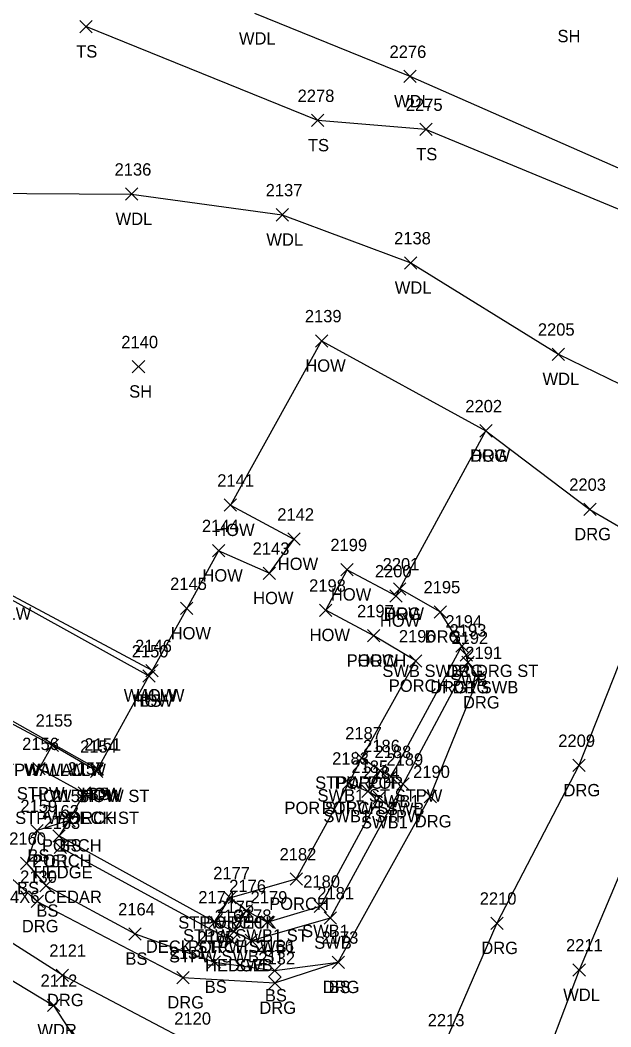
# Model space of a CAD drawing. Extents: x 1885914 to 1887218, y 756253 to 760620.
# Drawn here: x 1886470.3 to 1886566, y 760195 to 760358 of the extents above; entities that cross this region are included whole.
import ezdxf

# ---------------------------------------------------------------- set-up
doc = ezdxf.new("R2010")
doc.units = 0
for name, color, linetype in [('L_A', 7, 'Continuous'), ('L_C', 7, 'Continuous'), ('L_I', 7, 'Continuous'), ('L_TIC', 7, 'Continuous'), ('LAHR', 7, 'Continuous'), ('LAWA', 7, 'Continuous'), ('LBC', 7, 'Continuous'), ('LBF', 7, 'Continuous'), ('LELB', 7, 'Continuous'), ('LW', 7, 'Continuous'), ('R_A', 7, 'Continuous'), ('R_I', 7, 'Continuous'), ('R_TIC', 7, 'Continuous'), ('RDG', 7, 'Continuous'), ('RSW', 7, 'Continuous')]:
    doc.layers.add(name, color=color, linetype=linetype)

msp = doc.modelspace()

# ---------------------------------------------------------------- linework, layer by layer
at = {"layer": 'L_TIC'}
for points in [[(1886480, 760355.9), (1886482, 760357.9)], [(1886482, 760355.9), (1886480, 760357.9)], [(1886532.46, 760347.84), (1886534.46, 760349.84)], [(1886534.46, 760347.84), (1886532.46, 760349.84)], [(1886517.52, 760340.71), (1886519.52, 760342.71)], [(1886519.52, 760340.71), (1886517.52, 760342.71)], [(1886535.04, 760339.26), (1886537.04, 760341.26)], [(1886537.04, 760339.26), (1886535.04, 760341.26)], [(1886487.37, 760328.78), (1886489.37, 760330.78)], [(1886489.37, 760328.78), (1886487.37, 760330.78)], [(1886511.78, 760325.43), (1886513.78, 760327.43)], [(1886513.78, 760325.43), (1886511.78, 760327.43)], [(1886532.57, 760317.65), (1886534.57, 760319.65)], [(1886534.57, 760317.65), (1886532.57, 760319.65)], [(1886518.13, 760305.03), (1886520.13, 760307.03)], [(1886520.13, 760305.03), (1886518.13, 760307.03)], [(1886518.13, 760305.03), (1886520.13, 760307.03)], [(1886520.13, 760305.03), (1886518.13, 760307.03)], [(1886556.49, 760302.87), (1886558.49, 760304.87)], [(1886558.49, 760302.87), (1886556.49, 760304.87)], [(1886556.49, 760302.87), (1886558.49, 760304.87)], [(1886558.49, 760302.87), (1886556.49, 760304.87)], [(1886488.5, 760300.84), (1886490.5, 760302.84)], [(1886490.5, 760300.84), (1886488.5, 760302.84)], [(1886544.75, 760290.46), (1886546.75, 760292.46)], [(1886546.75, 760290.46), (1886544.75, 760292.46)], [(1886544.75, 760290.46), (1886546.75, 760292.46)], [(1886546.75, 760290.46), (1886544.75, 760292.46)], [(1886503.38, 760278.43), (1886505.38, 760280.43)], [(1886505.38, 760278.43), (1886503.38, 760280.43)], [(1886513.67, 760272.93), (1886515.67, 760274.93)], [(1886515.67, 760272.93), (1886513.67, 760274.93)], [(1886501.46, 760271.06), (1886503.46, 760273.06)], [(1886503.46, 760271.06), (1886501.46, 760273.06)], [(1886522.26, 760267.98), (1886524.26, 760269.98)], [(1886524.26, 760267.98), (1886522.26, 760269.98)], [(1886509.68, 760267.4), (1886511.68, 760269.4)], [(1886511.68, 760267.4), (1886509.68, 760269.4)], [(1886530.8, 760264.86), (1886532.8, 760266.86)], [(1886532.8, 760264.86), (1886530.8, 760266.86)], [(1886530.19, 760263.74), (1886532.19, 760265.74)], [(1886532.19, 760263.74), (1886530.19, 760265.74)], [(1886496.31, 760261.7), (1886498.31, 760263.7)], [(1886498.31, 760261.7), (1886496.31, 760263.7)], [(1886518.82, 760261.42), (1886520.82, 760263.42)], [(1886520.82, 760261.42), (1886518.82, 760263.42)], [(1886526.58, 760257.28), (1886528.58, 760259.28)], [(1886528.58, 760257.28), (1886526.58, 760259.28)], [(1886526.58, 760257.28), (1886528.58, 760259.28)], [(1886528.58, 760257.28), (1886526.58, 760259.28)], [(1886490.7, 760251.64), (1886492.7, 760253.64)], [(1886492.7, 760251.64), (1886490.7, 760253.64)], [(1886490.7, 760251.64), (1886492.7, 760253.64)], [(1886492.7, 760251.64), (1886490.7, 760253.64)], [(1886533.39, 760253.21), (1886535.39, 760255.21)], [(1886535.39, 760253.21), (1886533.39, 760255.21)], [(1886490.19, 760250.78), (1886492.19, 760252.78)], [(1886492.19, 760250.78), (1886490.19, 760252.78)], [(1886490.19, 760250.78), (1886492.19, 760252.78)], [(1886492.19, 760250.78), (1886490.19, 760252.78)], [(1886474.54, 760239.57), (1886476.54, 760241.57)], [(1886476.54, 760239.57), (1886474.54, 760241.57)], [(1886474.54, 760239.57), (1886476.54, 760241.57)], [(1886476.54, 760239.57), (1886474.54, 760241.57)], [(1886524.65, 760237.51), (1886526.65, 760239.51)], [(1886526.65, 760237.51), (1886524.65, 760239.51)], [(1886524.65, 760237.51), (1886526.65, 760239.51)], [(1886526.65, 760237.51), (1886524.65, 760239.51)], [(1886472.41, 760235.78), (1886474.41, 760237.78)], [(1886474.41, 760235.78), (1886472.41, 760237.78)], [(1886481.74, 760235.36), (1886483.74, 760237.36)], [(1886483.74, 760235.36), (1886481.74, 760237.36)], [(1886481.74, 760235.36), (1886483.74, 760237.36)], [(1886483.74, 760235.36), (1886481.74, 760237.36)], [(1886481.86, 760235.69), (1886483.86, 760237.69)], [(1886483.86, 760235.69), (1886481.86, 760237.69)], [(1886481.86, 760235.69), (1886483.86, 760237.69)], [(1886483.86, 760235.69), (1886481.86, 760237.69)], [(1886527.61, 760235.44), (1886529.61, 760237.44)], [(1886529.61, 760235.44), (1886527.61, 760237.44)], [(1886522.55, 760233.42), (1886524.55, 760235.42)], [(1886524.55, 760233.42), (1886522.55, 760235.42)], [(1886522.55, 760233.42), (1886524.55, 760235.42)], [(1886524.55, 760233.42), (1886522.55, 760235.42)], [(1886525.66, 760232.09), (1886527.66, 760234.09)], [(1886527.66, 760232.09), (1886525.66, 760234.09)], [(1886479.72, 760231.81), (1886481.72, 760233.81)], [(1886481.72, 760231.81), (1886479.72, 760233.81)], [(1886479.72, 760231.81), (1886481.72, 760233.81)], [(1886481.72, 760231.81), (1886479.72, 760233.81)], [(1886477.24, 760227.35), (1886479.24, 760229.35)], [(1886479.24, 760227.35), (1886477.24, 760229.35)], [(1886477.24, 760227.35), (1886479.24, 760229.35)], [(1886479.24, 760227.35), (1886477.24, 760229.35)], [(1886472.08, 760225.73), (1886474.08, 760227.73)], [(1886474.08, 760225.73), (1886472.08, 760227.73)], [(1886475.64, 760224.88), (1886477.64, 760226.88)], [(1886477.64, 760224.88), (1886475.64, 760226.88)], [(1886475.85, 760223.01), (1886477.85, 760225.01)], [(1886477.85, 760223.01), (1886475.85, 760225.01)], [(1886470.4, 760220.44), (1886472.4, 760222.44)], [(1886472.4, 760220.44), (1886470.4, 760222.44)], [(1886514.03, 760217.91), (1886516.03, 760219.91)], [(1886516.03, 760217.91), (1886514.03, 760219.91)], [(1886514.03, 760217.91), (1886516.03, 760219.91)], [(1886516.03, 760217.91), (1886514.03, 760219.91)], [(1886473.53, 760216.8), (1886475.53, 760218.8)], [(1886475.53, 760216.8), (1886473.53, 760218.8)], [(1886503.29, 760214.87), (1886505.29, 760216.87)], [(1886505.29, 760214.87), (1886503.29, 760216.87)], [(1886503.29, 760214.87), (1886505.29, 760216.87)], [(1886505.29, 760214.87), (1886503.29, 760216.87)], [(1886505.94, 760212.78), (1886507.94, 760214.78)], [(1886507.94, 760212.78), (1886505.94, 760214.78)], [(1886500.88, 760210.95), (1886502.88, 760212.95)], [(1886502.88, 760210.95), (1886500.88, 760212.95)], [(1886500.88, 760210.95), (1886502.88, 760212.95)], [(1886502.88, 760210.95), (1886500.88, 760212.95)], [(1886503.96, 760209.4), (1886505.96, 760211.4)], [(1886505.96, 760209.4), (1886503.96, 760211.4)], [(1886487.94, 760209.01), (1886489.94, 760211.01)], [(1886489.94, 760209.01), (1886487.94, 760211.01)], [(1886503.57, 760207.95), (1886505.57, 760209.95)], [(1886505.57, 760207.95), (1886503.57, 760209.95)], [(1886500.78, 760204.46), (1886502.78, 760206.46)], [(1886502.78, 760204.46), (1886500.78, 760206.46)], [(1886520.83, 760204.43), (1886522.83, 760206.43)], [(1886522.83, 760204.43), (1886520.83, 760206.43)], [(1886510.52, 760203.08), (1886512.52, 760205.08)], [(1886512.52, 760203.08), (1886510.52, 760205.08)], [(1886559.84, 760203.17), (1886561.84, 760205.17)], [(1886561.84, 760203.17), (1886559.84, 760205.17)], [(1886474.76, 760197.45), (1886476.76, 760199.45)], [(1886476.76, 760197.45), (1886474.76, 760199.45)]]:
    msp.add_lwpolyline(points, dxfattribs=at)
at = {"layer": 'LAHR'}
msp.add_lwpolyline([(1886476.85, 760224.01), (1886504.57, 760208.95)], dxfattribs=at)
at = {"layer": 'LAWA'}
for points in [[(1886557.49, 760303.87), (1886591.46, 760287.38), (1886586.6, 760261.32), (1886572.4, 760231.51), (1886560.84, 760204.17), (1886553.53, 760184.95), (1886554.61, 760165.79), (1886555.43, 760150.16), (1886559.73, 760135.93), (1886571.71, 760133.88), (1886584.52, 760154.18), (1886595.31, 760177.7), (1886612.55, 760208.5), (1886627.73, 760237.63), (1886641.55, 760264.82), (1886659.69, 760306.49), (1886641.28, 760308.88), (1886618.53, 760315.27), (1886578.46, 760329), (1886533.46, 760348.84), (1886508.34, 760359)], [(1886462.92, 760329.94), (1886488.37, 760329.78), (1886512.78, 760326.43), (1886533.57, 760318.65), (1886557.49, 760303.87)], [(1886416.83, 760225.49), (1886440.02, 760212.45), (1886451.63, 760212.99), (1886475.76, 760198.45), (1886488.7, 760178.57), (1886513.46, 760174.14), (1886520.82, 760161.01), (1886535.34, 760123.1)]]:
    msp.add_lwpolyline(points, dxfattribs=at)
at = {"layer": 'LBC'}
for points in [[(1886519.13, 760306.03), (1886504.38, 760279.43), (1886514.67, 760273.93), (1886510.68, 760268.4), (1886502.46, 760272.06), (1886497.31, 760262.7), (1886491.7, 760252.64), (1886491.19, 760251.78), (1886482.86, 760236.69), (1886482.74, 760236.36)], [(1886519.13, 760306.03), (1886545.75, 760291.46)], [(1886527.58, 760258.28), (1886519.82, 760262.42), (1886523.26, 760268.98), (1886531.19, 760264.74), (1886531.8, 760265.86), (1886545.75, 760291.46)]]:
    msp.add_lwpolyline(points, dxfattribs=at)
at = {"layer": 'LBF'}
for points in [[(1886515.03, 760218.91), (1886523.55, 760234.42), (1886525.65, 760238.51), (1886534.39, 760254.21), (1886527.58, 760258.28)], [(1886482.74, 760236.36), (1886475.54, 760240.57), (1886473.41, 760236.78), (1886480.72, 760232.81)], [(1886523.55, 760234.42), (1886526.66, 760233.09), (1886528.61, 760236.44), (1886525.65, 760238.51)], [(1886480.72, 760232.81), (1886478.24, 760228.35), (1886476.64, 760225.88), (1886501.88, 760211.95), (1886504.29, 760215.87), (1886515.03, 760218.91)], [(1886501.88, 760211.95), (1886504.96, 760210.4), (1886506.94, 760213.78), (1886504.29, 760215.87)]]:
    msp.add_lwpolyline(points, dxfattribs=at)
at = {"layer": 'LELB'}
for points in [[(1886641.28, 760308.88), (1886618.98, 760308.84), (1886580.48, 760321.86), (1886536.04, 760340.26), (1886518.52, 760341.71), (1886481, 760356.9)], [(1886466.56, 760265.9), (1886466.42, 760265.52), (1886491.19, 760251.78)], [(1886482.86, 760236.69), (1886455.65, 760252.02)], [(1886478.24, 760228.35), (1886473.08, 760226.73), (1886471.4, 760221.44), (1886474.53, 760217.8), (1886488.94, 760210.01), (1886501.78, 760205.46), (1886511.52, 760204.08), (1886521.83, 760205.43)]]:
    msp.add_lwpolyline(points, dxfattribs=at)
at = {"layer": 'LW'}
for points in [[(1886491.7, 760252.64), (1886466.93, 760265.9)], [(1886456.21, 760250.87), (1886475.54, 760240.57)]]:
    msp.add_lwpolyline(points, dxfattribs=at)
at = {"layer": 'R_TIC'}
for points in [[(1886544.75, 760290.46), (1886546.75, 760292.46)], [(1886546.75, 760290.46), (1886544.75, 760292.46)], [(1886561.57, 760277.75), (1886563.57, 760279.75)], [(1886563.57, 760277.75), (1886561.57, 760279.75)], [(1886530.8, 760264.86), (1886532.8, 760266.86)], [(1886532.8, 760264.86), (1886530.8, 760266.86)], [(1886537.34, 760261.15), (1886539.34, 760263.15)], [(1886539.34, 760261.15), (1886537.34, 760263.15)], [(1886540.87, 760255.61), (1886542.87, 760257.61)], [(1886542.87, 760255.61), (1886540.87, 760257.61)], [(1886540.87, 760255.61), (1886542.87, 760257.61)], [(1886542.87, 760255.61), (1886540.87, 760257.61)], [(1886540.87, 760255.61), (1886542.87, 760257.61)], [(1886542.87, 760255.61), (1886540.87, 760257.61)], [(1886541.57, 760254.16), (1886543.57, 760256.16)], [(1886543.57, 760254.16), (1886541.57, 760256.16)], [(1886541.85, 760252.96), (1886543.85, 760254.96)], [(1886543.85, 760252.96), (1886541.85, 760254.96)], [(1886541.85, 760252.96), (1886543.85, 760254.96)], [(1886543.85, 760252.96), (1886541.85, 760254.96)], [(1886543.54, 760250.51), (1886545.54, 760252.51)], [(1886545.54, 760250.51), (1886543.54, 760252.51)], [(1886527.61, 760235.44), (1886529.61, 760237.44)], [(1886529.61, 760235.44), (1886527.61, 760237.44)], [(1886559.81, 760236.29), (1886561.81, 760238.29)], [(1886561.81, 760236.29), (1886559.81, 760238.29)], [(1886529.4, 760234.49), (1886531.4, 760236.49)], [(1886531.4, 760234.49), (1886529.4, 760236.49)], [(1886525.66, 760232.09), (1886527.66, 760234.09)], [(1886527.66, 760232.09), (1886525.66, 760234.09)], [(1886531.34, 760233.26), (1886533.34, 760235.26)], [(1886533.34, 760233.26), (1886531.34, 760235.26)], [(1886527.48, 760231.1), (1886529.48, 760233.1)], [(1886529.48, 760231.1), (1886527.48, 760233.1)], [(1886535.74, 760231.26), (1886537.74, 760233.26)], [(1886537.74, 760231.26), (1886535.74, 760233.26)], [(1886472.12, 760214.28), (1886474.12, 760216.28)], [(1886474.12, 760214.28), (1886472.12, 760216.28)], [(1886505.94, 760212.78), (1886507.94, 760214.78)], [(1886507.94, 760212.78), (1886505.94, 760214.78)], [(1886517.95, 760213.5), (1886519.95, 760215.5)], [(1886519.95, 760213.5), (1886517.95, 760215.5)], [(1886509.35, 760210.94), (1886511.35, 760212.94)], [(1886511.35, 760210.94), (1886509.35, 760212.94)], [(1886519.58, 760211.61), (1886521.58, 760213.61)], [(1886521.58, 760211.61), (1886519.58, 760213.61)], [(1886503.96, 760209.4), (1886505.96, 760211.4)], [(1886505.96, 760209.4), (1886503.96, 760211.4)], [(1886546.52, 760210.75), (1886548.52, 760212.75)], [(1886548.52, 760210.75), (1886546.52, 760212.75)], [(1886506.78, 760207.97), (1886508.78, 760209.97)], [(1886508.78, 760207.97), (1886506.78, 760209.97)], [(1886520.83, 760204.43), (1886522.83, 760206.43)], [(1886522.83, 760204.43), (1886520.83, 760206.43)], [(1886476.19, 760202.32), (1886478.19, 760204.32)], [(1886478.19, 760202.32), (1886476.19, 760204.32)], [(1886495.68, 760201.95), (1886497.68, 760203.95)], [(1886497.68, 760201.95), (1886495.68, 760203.95)], [(1886510.58, 760201.07), (1886512.58, 760203.07)], [(1886512.58, 760201.07), (1886510.58, 760203.07)]]:
    msp.add_lwpolyline(points, dxfattribs=at)
at = {"layer": 'RDG'}
for points in [[(1886545.75, 760291.46), (1886562.57, 760278.75), (1886574.43, 760271.84), (1886560.81, 760237.29), (1886547.52, 760211.75), (1886539.01, 760192.05), (1886538.13, 760179.08), (1886537.48, 760165.92), (1886548.05, 760139.99), (1886558.75, 760116.26), (1886568.3, 760110.67), (1886571.83, 760112.64), (1886573.56, 760113.12)], [(1886541.87, 760256.61), (1886538.34, 760262.15), (1886531.8, 760265.86)], [(1886456.58, 760230.17), (1886473.12, 760215.28), (1886496.68, 760202.95), (1886511.58, 760202.07), (1886521.83, 760205.43), (1886536.74, 760232.26), (1886544.54, 760251.51), (1886542.85, 760253.96)], [(1886454.48, 760119.53), (1886487.38, 760097.68), (1886513.73, 760081.78), (1886534.81, 760073.6), (1886543.18, 760075.46), (1886550.17, 760080.85), (1886553.86, 760089.33), (1886543.64, 760117.47), (1886531.81, 760149.73), (1886525.16, 760171.12), (1886518.53, 760180.07), (1886498.07, 760192.32), (1886477.19, 760203.32), (1886461.39, 760213.36)]]:
    msp.add_lwpolyline(points, dxfattribs=at)
at = {"layer": 'RSW'}
for points in [[(1886504.96, 760210.4), (1886507.78, 760208.97), (1886520.58, 760212.61), (1886532.34, 760234.26), (1886542.85, 760253.96), (1886542.57, 760255.16), (1886541.87, 760256.61)], [(1886528.61, 760236.44), (1886530.4, 760235.49), (1886541.87, 760256.61)], [(1886506.94, 760213.78), (1886510.35, 760211.94), (1886518.95, 760214.5), (1886528.48, 760232.1), (1886526.66, 760233.09)]]:
    msp.add_lwpolyline(points, dxfattribs=at)

# ---------------------------------------------------------------- texts
at = {"layer": 'L_A'}
for s, p in [('SH', (1886557.33, 760354.37)), ('WDL', (1886505.76, 760354)), ('TS', (1886479.41, 760351.9)), ('WDL', (1886530.87, 760343.84)), ('TS', (1886516.93, 760336.71)), ('TS', (1886534.45, 760335.26)), ('WDL', (1886485.79, 760324.78)), ('WDL', (1886510.2, 760321.43)), ('WDL', (1886530.99, 760313.65)), ('HOW', (1886516.51, 760301.03)), ('HOW', (1886516.51, 760301.03)), ('WDL', (1886554.91, 760298.87)), ('WDL', (1886554.91, 760298.87)), ('SH', (1886487.99, 760296.84)), ('HOW', (1886543.14, 760286.46)), ('HOW', (1886543.14, 760286.46)), ('HOW', (1886501.76, 760274.43)), ('HOW', (1886512.05, 760268.93)), ('HOW', (1886499.85, 760267.06)), ('HOW', (1886508.06, 760263.4)), ('HOW', (1886520.65, 760263.98)), ('WALLW', (1886462.34, 760260.9)), ('HOW', (1886528.58, 760259.74)), ('HOW', (1886529.18, 760260.86)), ('HOW', (1886494.7, 760257.7)), ('HOW', (1886517.2, 760257.42)), ('PORCH', (1886523.2, 760253.28)), ('HOW', (1886524.96, 760253.28)), ('PORCH', (1886530.02, 760249.21)), ('WALLW', (1886487.12, 760247.64)), ('HOW', (1886488.57, 760246.78)), ('HOW', (1886489.09, 760247.64)), ('BS', (1886489.63, 760246.78)), ('STPW WALLW', (1886465.95, 760235.57)), ('WALLW', (1886470.96, 760235.57)), ('STPW POR', (1886518.1, 760233.51)), ('PORCH', (1886521.28, 760233.51)), ('STPW', (1886469.8, 760231.78)), ('HOW STPW ST', (1886472.11, 760231.36)), ('HOW', (1886480.12, 760231.36)), ('HOW', (1886480.25, 760231.69)), ('BS', (1886481.3, 760231.69)), ('SWB1 ST STPW', (1886518.48, 760231.44)), ('POR STPW ST', (1886513.13, 760229.42)), ('PORCH', (1886519.17, 760229.42)), ('STPW DECK ST', (1886469.53, 760227.81)), ('PORCH', (1886476.34, 760227.81)), ('SWB1 STPW', (1886519.43, 760228.09)), ('PORCH', (1886473.87, 760223.35)), ('BS', (1886476.69, 760223.35)), ('BS', (1886471.52, 760221.73)), ('PORCH', (1886472.26, 760220.88)), ('HEDGE', (1886472.55, 760219.01)), ('BS', (1886469.84, 760216.44)), ('BS', (1886472.97, 760212.8)), ('PORCH', (1886510.66, 760213.91)), ('PORCH', (1886510.66, 760213.91)), ('STPW DECK', (1886495.93, 760210.87)), ('PORCH', (1886499.92, 760210.87)), ('STPW SWB1 ST', (1886496.71, 760208.78)), ('DECK STPW ST', (1886490.69, 760206.95)), ('PORCH', (1886497.5, 760206.95)), ('BS', (1886487.38, 760205.01)), ('STPW SWB ST', (1886494.44, 760205.4)), ('HEDGE', (1886500.27, 760203.95)), ('BS', (1886500.23, 760200.46)), ('BS', (1886520.27, 760200.43)), ('BS', (1886509.96, 760199.08)), ('WDL', (1886558.25, 760199.17)), ('WDR', (1886473.13, 760193.45))]:
    msp.add_text(s, height=2, dxfattribs=at).set_placement(p)
at = {"layer": 'L_C'}
msp.add_text('4X6 CEDAR', height=2, dxfattribs=at).set_placement((1886468.71, 760215.01))
at = {"layer": 'L_I'}
for s, p in [('2276', (1886530.14, 760351.84)), ('2278', (1886515.26, 760344.71)), ('2275', (1886532.78, 760343.26)), ('2136', (1886485.63, 760332.78)), ('2137', (1886510.09, 760329.43)), ('2138', (1886530.88, 760321.65)), ('2139', (1886516.43, 760309.03)), ('2139', (1886516.43, 760309.03)), ('2205', (1886554.15, 760306.87)), ('2205', (1886554.15, 760306.87)), ('2140', (1886486.72, 760304.84)), ('2202', (1886542.41, 760294.46)), ('2202', (1886542.41, 760294.46)), ('2141', (1886502.25, 760282.43)), ('2142', (1886511.97, 760276.93)), ('2144', (1886499.77, 760275.06)), ('2143', (1886507.98, 760271.4)), ('2199', (1886520.56, 760271.98)), ('2201', (1886529.02, 760268.86)), ('2200', (1886527.77, 760267.74)), ('2145', (1886494.62, 760265.7)), ('2198', (1886517.12, 760265.42)), ('2197', (1886524.88, 760261.28)), ('2197', (1886524.88, 760261.28)), ('2196', (1886531.65, 760257.21)), ('2146', (1886488.95, 760255.64)), ('2146', (1886488.95, 760255.64)), ('2150', (1886488.41, 760254.78)), ('2150', (1886488.41, 760254.78)), ('2155', (1886472.85, 760243.57)), ('2155', (1886472.85, 760243.57)), ('2187', (1886522.96, 760241.51)), ('2187', (1886522.96, 760241.51)), ('2156', (1886470.66, 760239.78)), ('2154', (1886480.04, 760239.36)), ('2154', (1886480.04, 760239.36)), ('2151', (1886480.74, 760239.69)), ('2151', (1886480.74, 760239.69)), ('2186', (1886525.86, 760239.44)), ('2183', (1886520.85, 760237.42)), ('2183', (1886520.85, 760237.42)), ('2157', (1886478.02, 760235.81)), ('2157', (1886478.02, 760235.81)), ('2185', (1886523.97, 760236.09)), ('2158', (1886475.55, 760231.35)), ('2158', (1886475.55, 760231.35)), ('2159', (1886470.38, 760229.73)), ('2162', (1886473.9, 760228.88)), ('2163', (1886474.11, 760227.01)), ('2160', (1886468.57, 760224.44)), ('2161', (1886472.36, 760220.8)), ('2182', (1886512.34, 760221.91)), ('2182', (1886512.34, 760221.91)), ('2177', (1886501.6, 760218.87)), ('2177', (1886501.6, 760218.87)), ('2176', (1886504.19, 760216.78)), ('2174', (1886499.18, 760214.95)), ('2174', (1886499.18, 760214.95)), ('2164', (1886486.2, 760213.01)), ('2175', (1886502.26, 760213.4)), ('2167', (1886501.83, 760211.95)), ('2165', (1886499.04, 760208.46)), ('2173', (1886519.14, 760208.43)), ('2166', (1886508.72, 760207.08)), ('2211', (1886558.71, 760207.17)), ('2112', (1886473.64, 760201.45))]:
    msp.add_text(s, height=2, dxfattribs=at).set_placement(p)
at = {"layer": 'R_A'}
for s, p in [('DRG', (1886543.24, 760286.46)), ('DRG', (1886560.05, 760273.75)), ('DRG', (1886529.28, 760260.86)), ('DRG', (1886535.83, 760257.15)), ('SWB SWB1 DRG ST', (1886528.97, 760251.61)), ('SWB SWB1 DRG ST', (1886528.97, 760251.61)), ('DRG', (1886539.36, 760251.61)), ('SWB', (1886539.93, 760250.16)), ('DRG1 SWB', (1886536.72, 760248.96)), ('DRG', (1886540.34, 760248.96)), ('DRG', (1886542.03, 760246.51)), ('DRG', (1886558.3, 760232.29)), ('SWB1 ST STPW', (1886518.48, 760231.44)), ('SWB1', (1886527.44, 760230.49)), ('SWB', (1886529.7, 760229.26)), ('SWB1 STPW', (1886519.43, 760228.09)), ('DRG', (1886534.23, 760227.26)), ('SWB1', (1886525.52, 760227.1)), ('DRG', (1886470.61, 760210.28)), ('SWB1', (1886515.99, 760209.5)), ('STPW SWB1 ST', (1886496.71, 760208.78)), ('SWB', (1886517.94, 760207.61)), ('SWB1', (1886507.39, 760206.94)), ('DRG', (1886545, 760206.75)), ('STPW SWB ST', (1886494.44, 760205.4)), ('SWB', (1886505.14, 760203.97)), ('DRG', (1886519.32, 760200.43)), ('DRG', (1886474.68, 760198.32)), ('DRG', (1886494.17, 760197.95)), ('DRG', (1886509.07, 760197.07))]:
    msp.add_text(s, height=2, dxfattribs=at).set_placement(p)
at = {"layer": 'R_I'}
for s, p in [('2202', (1886542.41, 760294.46)), ('2203', (1886559.23, 760281.75)), ('2201', (1886529.02, 760268.86)), ('2195', (1886535.64, 760265.15)), ('2194', (1886539.18, 760259.61)), ('2194', (1886539.18, 760259.61)), ('2194', (1886539.18, 760259.61)), ('2193', (1886539.87, 760258.16)), ('2192', (1886540.16, 760256.96)), ('2192', (1886540.16, 760256.96)), ('2191', (1886542.41, 760254.51)), ('2209', (1886557.46, 760240.29)), ('2186', (1886525.86, 760239.44)), ('2188', (1886527.71, 760238.49)), ('2189', (1886529.64, 760237.26)), ('2185', (1886523.97, 760236.09)), ('2184', (1886525.78, 760235.1)), ('2190', (1886533.96, 760235.26)), ('2130', (1886470.34, 760218.28)), ('2180', (1886516.17, 760217.5)), ('2176', (1886504.19, 760216.78)), ('2179', (1886507.65, 760214.94)), ('2181', (1886518.45, 760215.61)), ('2210', (1886544.74, 760214.75)), ('2175', (1886502.26, 760213.4)), ('2178', (1886505.08, 760211.97)), ('2173', (1886519.14, 760208.43)), ('2121', (1886475.06, 760206.32)), ('2131', (1886494.56, 760205.95)), ('2132', (1886508.89, 760205.07)), ('2120', (1886495.29, 760195.32)), ('2213', (1886536.32, 760195.05))]:
    msp.add_text(s, height=2, dxfattribs=at).set_placement(p)

doc.saveas('drawing.dxf')
